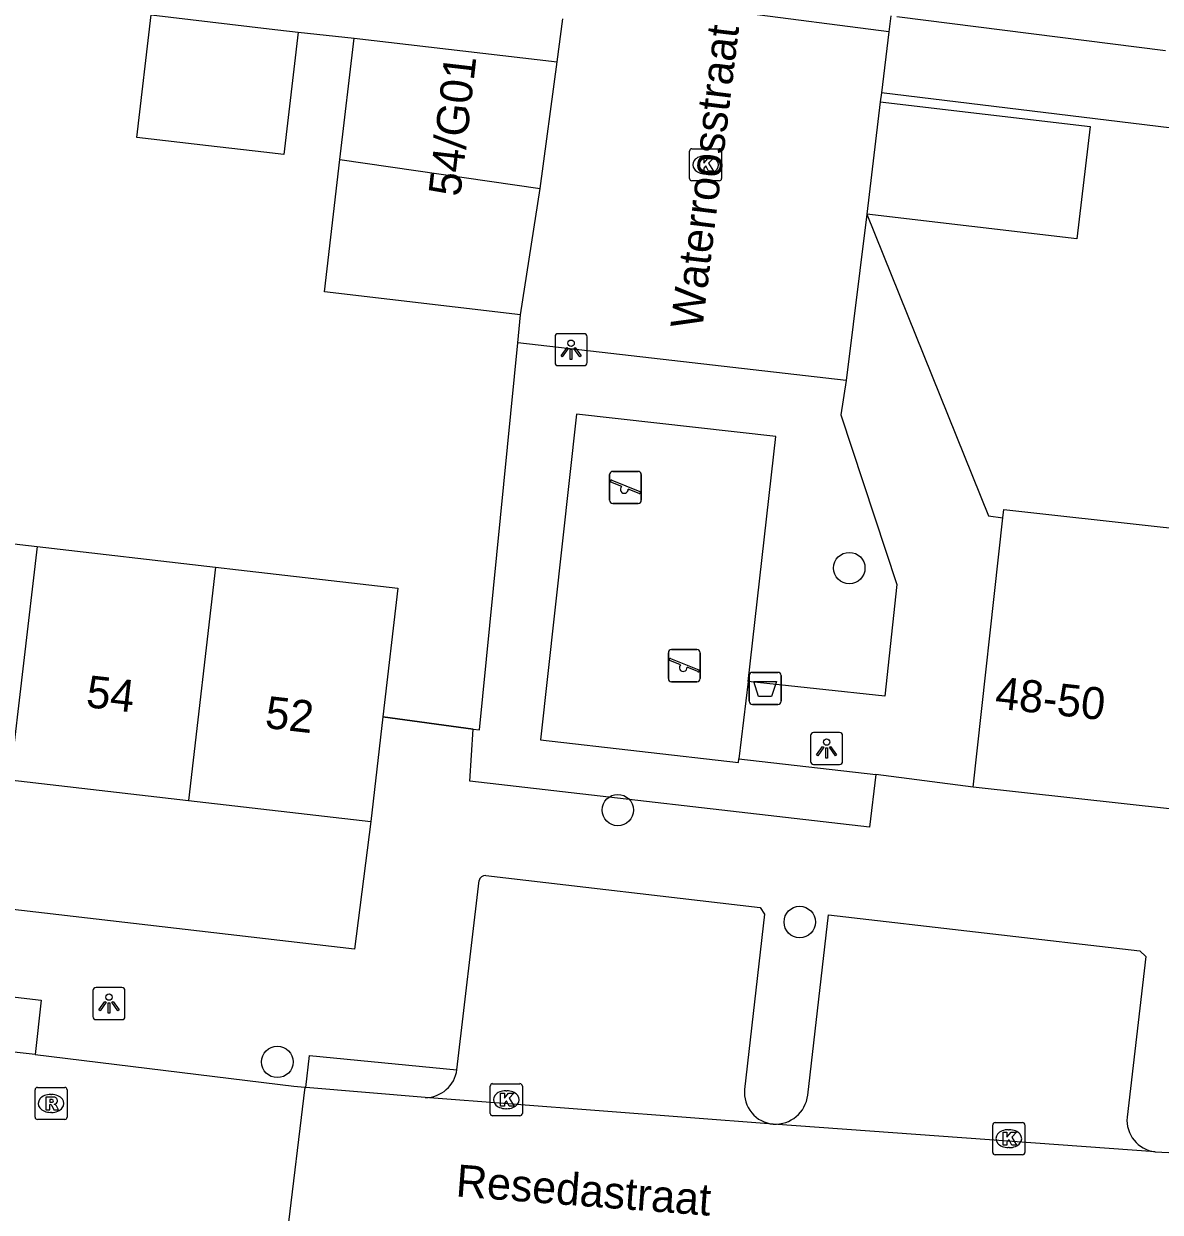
# Model space of a CAD drawing. Extents: x 162250 to 162654, y 380744 to 381605.
# Drawn here: x 162377.07 to 162412.48, y 380893.89 to 380930.93 of the extents above; entities that cross this region are included whole.
import ezdxf

# ---------------------------------------------------------------- set-up
doc = ezdxf.new("R2010")
doc.units = 0
for name, color, linetype in [('IMGEO_Afvalbak', 7, 'Continuous'), ('IMGEO_Boom', 7, 'Continuous'), ('IMGEO_Haag', 7, 'Continuous'), ('IMGEO_Kolk', 7, 'Continuous'), ('IMGEO_Lichtpunt', 7, 'Continuous'), ('IMGEO_Muur', 7, 'Continuous'), ('IMGEO_Openbare_ruimte_label', 7, 'Continuous'), ('IMGEO_Pand', 7, 'Continuous'), ('IMGEO_Pand_nummerreeks', 7, 'Continuous'), ('IMGEO_Rijbaan_lokaal_open', 7, 'Continuous'), ('IMGEO_Rioolput', 7, 'Continuous'), ('IMGEO_Speelvoorziening', 7, 'Continuous'), ('IMGEO_Voetpad_open', 7, 'Continuous')]:
    doc.layers.add(name, color=color, linetype=linetype)

msp = doc.modelspace()

# ---------------------------------------------------------------- linework, layer by layer
at = {"layer": 'IMGEO_Afvalbak'}
for p, q in [((162399.676, 380909.814), (162399.676, 380910.614)), ((162399.676, 380910.614), (162399.676, 380909.814)), ((162399.776, 380910.714), (162400.566, 380910.714)), ((162400.566, 380910.714), (162399.776, 380910.714)), ((162400.666, 380910.614), (162400.666, 380909.814)), ((162400.666, 380909.814), (162400.666, 380910.614)), ((162400.566, 380909.714), (162399.776, 380909.714)), ((162399.776, 380909.714), (162400.566, 380909.714))]:
    msp.add_line(p, q, dxfattribs=at)
msp.add_lwpolyline([(162399.819, 380910.428), (162400.523, 380910.428), (162400.374, 380909.958), (162399.968, 380909.958), (162399.819, 380910.428)], dxfattribs=at)
for centre, start, end in [((162399.776, 380910.614), 90, 180), ((162399.776, 380910.614), 90, 180), ((162400.566, 380910.614), 0, 90), ((162400.566, 380910.614), 360, 90), ((162399.776, 380909.814), 180, 270), ((162399.776, 380909.814), 180, 270), ((162400.566, 380909.814), 270, 0), ((162400.566, 380909.814), 270, 0)]:
    msp.add_arc(centre, 0.1, start, end, dxfattribs=at)
at = {"layer": 'IMGEO_Boom'}
for centre in [(162402.793, 380913.965), (162395.581, 380906.422), (162401.249, 380902.934), (162384.974, 380898.573)]:
    msp.add_circle(centre, 0.489, dxfattribs=at)
at = {"layer": 'IMGEO_Haag'}
for points in [[(162391.079, 380908.948), (162391.269, 380908.923), (162392.465, 380920.986)], [(162399.645, 380910.429), (162400.502, 380918.069), (162394.299, 380918.756), (162393.177, 380908.609), (162399.34, 380907.907), (162399.353, 380908.016)]]:
    msp.add_lwpolyline(points, dxfattribs=at)
at = {"layer": 'IMGEO_Kolk'}
for p, q in [((162397.815, 380926.106), (162397.815, 380926.958)), ((162397.89, 380927.032), (162398.742, 380927.032)), ((162398.303, 380926.812), (162398.328, 380926.812)), ((162398.816, 380926.958), (162398.816, 380926.106)), ((162398.742, 380926.032), (162397.89, 380926.032)), ((162398.326, 380926.252), (162398.301, 380926.252)), ((162391.606, 380896.97), (162391.606, 380897.822)), ((162391.681, 380897.896), (162392.533, 380897.896)), ((162392.607, 380897.822), (162392.607, 380896.97)), ((162392.094, 380897.676), (162392.119, 380897.676)), ((162392.117, 380897.116), (162392.092, 380897.116)), ((162392.533, 380896.896), (162391.681, 380896.896)), ((162407.262, 380895.756), (162407.262, 380896.608)), ((162407.337, 380896.682), (162408.189, 380896.682)), ((162407.75, 380896.462), (162407.775, 380896.462)), ((162408.263, 380896.608), (162408.263, 380895.756)), ((162408.189, 380895.682), (162407.337, 380895.682)), ((162407.773, 380895.902), (162407.748, 380895.902))]:
    msp.add_line(p, q, dxfattribs=at)
for points in [[(162397.815, 380926.106), (162397.815, 380926.958)], [(162397.89, 380927.032), (162398.742, 380927.032)], [(162398.136, 380926.732), (162398.259, 380926.732), (162398.259, 380926.581), (162398.389, 380926.732), (162398.553, 380926.732), (162398.407, 380926.581), (162398.56, 380926.332), (162398.408, 380926.332), (162398.323, 380926.496), (162398.259, 380926.429), (162398.259, 380926.332), (162398.136, 380926.332), (162398.136, 380926.732)], [(162398.816, 380926.958), (162398.816, 380926.106)], [(162398.742, 380926.032), (162397.89, 380926.032)], [(162391.606, 380896.97), (162391.606, 380897.822)], [(162391.681, 380897.896), (162392.533, 380897.896)], [(162392.607, 380897.822), (162392.607, 380896.97)], [(162391.927, 380897.596), (162392.05, 380897.596), (162392.05, 380897.445), (162392.18, 380897.596), (162392.344, 380897.596), (162392.198, 380897.445), (162392.351, 380897.196), (162392.199, 380897.196), (162392.114, 380897.36), (162392.05, 380897.293), (162392.05, 380897.196), (162391.927, 380897.196), (162391.927, 380897.596)], [(162392.533, 380896.896), (162391.681, 380896.896)], [(162407.262, 380895.756), (162407.262, 380896.608)], [(162407.337, 380896.682), (162408.189, 380896.682)], [(162407.583, 380896.382), (162407.706, 380896.382), (162407.706, 380896.231), (162407.836, 380896.382), (162408, 380896.382), (162407.854, 380896.231), (162408.007, 380895.982), (162407.855, 380895.982), (162407.77, 380896.146), (162407.706, 380896.079), (162407.706, 380895.982), (162407.583, 380895.982), (162407.583, 380896.382)], [(162408.263, 380896.608), (162408.263, 380895.756)], [(162408.189, 380895.682), (162407.337, 380895.682)]]:
    msp.add_lwpolyline(points, dxfattribs=at)
for centre, start, end in [((162397.892, 380926.956), 91.552, 178.448), ((162397.892, 380926.956), 91.552, 178.448), ((162398.74, 380926.956), 1.552, 88.448), ((162398.74, 380926.956), 1.552, 88.448), ((162397.892, 380926.108), 181.552, 268.448), ((162397.892, 380926.108), 181.552, 268.448), ((162398.74, 380926.108), 271.552, 358.448), ((162398.74, 380926.108), 271.552, 358.448), ((162391.683, 380897.82), 91.552, 178.448), ((162391.683, 380897.82), 91.552, 178.448), ((162392.531, 380897.82), 1.552, 88.448), ((162392.531, 380897.82), 1.552, 88.448), ((162391.683, 380896.972), 181.552, 268.448), ((162391.683, 380896.972), 181.552, 268.448), ((162392.531, 380896.972), 271.552, 358.448), ((162392.531, 380896.972), 271.552, 358.448), ((162407.339, 380896.606), 91.552, 178.448), ((162407.339, 380896.606), 91.552, 178.448), ((162408.187, 380896.606), 1.552, 88.448), ((162408.187, 380896.606), 1.552, 88.448), ((162407.339, 380895.758), 181.552, 268.448), ((162407.339, 380895.758), 181.552, 268.448), ((162408.187, 380895.758), 271.552, 358.448), ((162408.187, 380895.758), 271.552, 358.448)]:
    msp.add_arc(centre, 0.0765, start, end, dxfattribs=at)
for centre, major_axis, ratio, start_param, end_param in [((162398.302, 380926.532), (-0.387, 0.002), 0.722429, 4.712389, 7.853982), ((162398.327, 380926.532), (-0.39, 0.002), 0.717154, 1.570796, 4.712389), ((162392.093, 380897.396), (-0.387, 0.002), 0.722429, 4.712389, 7.853982), ((162392.118, 380897.396), (-0.39, 0.002), 0.717154, 1.570796, 4.712389), ((162407.749, 380896.182), (-0.387, 0.002), 0.722429, 4.712389, 7.853982), ((162407.774, 380896.182), (-0.39, 0.002), 0.717154, 1.570796, 4.712389)]:
    msp.add_ellipse(centre, major_axis=major_axis, ratio=ratio, start_param=start_param, end_param=end_param, dxfattribs=at)
at = {"layer": 'IMGEO_Lichtpunt'}
for p, q in [((162393.626, 380921.174), (162393.626, 380920.367)), ((162393.626, 380921.174), (162393.626, 380920.367)), ((162394.528, 380921.269), (162393.72, 380921.269)), ((162394.528, 380921.269), (162393.72, 380921.269)), ((162394.622, 380920.367), (162394.622, 380921.174)), ((162394.622, 380920.367), (162394.622, 380921.174)), ((162393.72, 380920.273), (162394.528, 380920.273)), ((162393.72, 380920.273), (162394.528, 380920.273)), ((162401.588, 380908.744), (162401.588, 380907.937)), ((162401.588, 380908.744), (162401.588, 380907.937)), ((162402.49, 380908.839), (162401.682, 380908.839)), ((162402.49, 380908.839), (162401.682, 380908.839)), ((162402.584, 380907.937), (162402.584, 380908.744)), ((162402.584, 380907.937), (162402.584, 380908.744)), ((162401.682, 380907.843), (162402.49, 380907.843)), ((162401.682, 380907.843), (162402.49, 380907.843)), ((162379.231, 380900.795), (162379.231, 380899.988)), ((162379.231, 380900.795), (162379.231, 380899.988)), ((162380.133, 380900.89), (162379.325, 380900.89)), ((162380.133, 380900.89), (162379.325, 380900.89)), ((162380.227, 380899.988), (162380.227, 380900.795)), ((162380.227, 380899.988), (162380.227, 380900.795)), ((162379.325, 380899.894), (162380.133, 380899.894)), ((162379.325, 380899.894), (162380.133, 380899.894))]:
    msp.add_line(p, q, dxfattribs=at)
for points in [[(162394, 380920.838), (162394.039, 380920.81), (162393.851, 380920.548), (162393.813, 380920.575), (162394, 380920.838)], [(162394.102, 380920.79), (162394.149, 380920.79), (162394.149, 380920.468), (162394.102, 380920.468), (162394.102, 380920.79)], [(162394.212, 380920.81), (162394.25, 380920.837), (162394.437, 380920.575), (162394.398, 380920.547), (162394.212, 380920.81)], [(162401.962, 380908.408), (162402.001, 380908.38), (162401.813, 380908.118), (162401.775, 380908.145), (162401.962, 380908.408)], [(162402.064, 380908.36), (162402.111, 380908.36), (162402.111, 380908.038), (162402.064, 380908.038), (162402.064, 380908.36)], [(162402.174, 380908.38), (162402.212, 380908.407), (162402.399, 380908.145), (162402.36, 380908.117), (162402.174, 380908.38)], [(162379.605, 380900.459), (162379.644, 380900.431), (162379.456, 380900.169), (162379.418, 380900.196), (162379.605, 380900.459)], [(162379.707, 380900.411), (162379.754, 380900.411), (162379.754, 380900.089), (162379.707, 380900.089), (162379.707, 380900.411)], [(162379.817, 380900.431), (162379.855, 380900.458), (162380.042, 380900.196), (162380.003, 380900.168), (162379.817, 380900.431)]]:
    msp.add_lwpolyline(points, dxfattribs=at)
for centre in [(162394.125, 380920.972), (162402.087, 380908.542), (162379.73, 380900.593)]:
    msp.add_circle(centre, 0.0994, dxfattribs=at)
for centre, start, end in [((162393.72, 380921.174), 90, 180), ((162393.72, 380921.174), 90, 180), ((162394.528, 380921.174), 0, 90), ((162394.528, 380921.174), 0, 90), ((162393.72, 380920.367), 180, 270), ((162393.72, 380920.367), 180, 270), ((162394.528, 380920.367), 270, 0), ((162394.528, 380920.367), 270, 360), ((162401.682, 380908.744), 90, 180), ((162401.682, 380908.744), 90, 180), ((162402.49, 380908.744), 0, 90), ((162402.49, 380908.744), 0, 90), ((162401.682, 380907.937), 180, 270), ((162401.682, 380907.937), 180, 270), ((162402.49, 380907.937), 270, 0), ((162402.49, 380907.937), 270, 360), ((162379.325, 380900.795), 90, 180), ((162379.325, 380900.795), 90, 180), ((162380.133, 380900.795), 0, 90), ((162380.133, 380900.795), 0, 90), ((162379.325, 380899.988), 180, 270), ((162379.325, 380899.988), 180, 270), ((162380.133, 380899.988), 270, 0), ((162380.133, 380899.988), 270, 360)]:
    msp.add_arc(centre, 0.0946, start, end, dxfattribs=at)
at = {"layer": 'IMGEO_Muur'}
for points in [[(162392.465, 380920.986), (162392.552, 380921.858)], [(162391.079, 380908.948), (162391.269, 380908.923), (162392.465, 380920.986)], [(162388.264, 380909.325), (162391.079, 380908.948)]]:
    msp.add_lwpolyline(points, dxfattribs=at)
at = {"layer": 'IMGEO_Pand'}
for points in [[(162385.623, 380930.668), (162385.179, 380926.849), (162384.55, 380926.922), (162382.83, 380927.122), (162380.598, 380927.382), (162381.042, 380931.201)], [(162381.042, 380931.201), (162384.718, 380930.773), (162384.994, 380930.741), (162385.623, 380930.668)], [(162404.27, 380931.15), (162412.639, 380930.091)], [(162386.923, 380926.699), (162387.365, 380930.48)], [(162387.365, 380930.48), (162393.695, 380929.741)], [(162393.167, 380925.793), (162393.695, 380929.741)], [(162403.759, 380928.497), (162410.295, 380927.721), (162409.879, 380924.221), (162403.344, 380924.995)], [(162403.759, 380928.497), (162403.344, 380924.995)], [(162392.552, 380921.858), (162386.44, 380922.572), (162386.923, 380926.699)], [(162386.923, 380926.699), (162393.167, 380925.793)], [(162392.552, 380921.858), (162393.167, 380925.793)], [(162407.575, 380915.525), (162407.604, 380915.79), (162412.574, 380915.242), (162413.861, 380915.1)], [(162371.924, 380915.282), (162377.487, 380914.637)], [(162406.649, 380907.132), (162407.575, 380915.525)], [(162377.487, 380914.637), (162376.642, 380907.369)], [(162377.487, 380914.637), (162383.048, 380913.992)], [(162383.048, 380913.992), (162382.204, 380906.725)], [(162383.048, 380913.992), (162383.762, 380913.91), (162388.728, 380913.334), (162388.264, 380909.325)], [(162388.264, 380909.325), (162387.886, 380906.066)], [(162376.642, 380907.369), (162382.204, 380906.725)], [(162412.864, 380906.447), (162406.649, 380907.132)], [(162382.204, 380906.725), (162387.886, 380906.066)]]:
    msp.add_lwpolyline(points, dxfattribs=at)
at = {"layer": 'IMGEO_Rijbaan_lokaal_open'}
for points in [[(162404.024, 380930.68), (162399.359, 380931.282), (162401.19, 380947.056)], [(162393.695, 380929.741), (162393.868, 380931.08)], [(162404.024, 380930.68), (162403.792, 380928.77)], [(162403.792, 380928.77), (162403.759, 380928.497)], [(162403.344, 380924.995), (162402.7, 380919.808)], [(162392.465, 380920.986), (162392.552, 380921.858)], [(162402.7, 380919.808), (162392.465, 380920.986)], [(162377.427, 380898.803), (162372.076, 380899.395)], [(162377.427, 380898.803), (162385.493, 380897.823), (162385.826, 380897.783)], [(162385.826, 380897.783), (162385.279, 380893.239)], [(162385.826, 380897.783), (162385.866, 380897.778)], [(162389.579, 380897.463), (162385.866, 380897.778)], [(162400.423, 380896.635), (162389.579, 380897.463)], [(162412.32, 380895.776), (162400.423, 380896.635)], [(162412.32, 380895.776), (162412.957, 380895.742)]]:
    msp.add_lwpolyline(points, dxfattribs=at)
at = {"layer": 'IMGEO_Rioolput'}
for p, q in [((162377.426, 380896.854), (162377.426, 380897.706)), ((162377.501, 380897.78), (162378.353, 380897.78)), ((162377.914, 380897.56), (162377.939, 380897.56)), ((162378.427, 380897.706), (162378.427, 380896.854)), ((162378.353, 380896.78), (162377.501, 380896.78)), ((162377.937, 380897), (162377.912, 380897))]:
    msp.add_line(p, q, dxfattribs=at)
for points in [[(162377.426, 380896.854), (162377.426, 380897.706)], [(162377.501, 380897.78), (162378.353, 380897.78)], [(162378.015, 380897.478), (162377.763, 380897.48), (162377.763, 380897.08)], [(162378.427, 380897.706), (162378.427, 380896.854)], [(162377.763, 380897.08), (162377.887, 380897.08), (162377.887, 380897.242), (162377.898, 380897.242)], [(162377.941, 380897.399), (162377.887, 380897.399), (162377.887, 380897.318)], [(162377.887, 380897.318), (162377.939, 380897.318)], [(162377.945, 380897.213), (162378.016, 380897.08), (162378.156, 380897.08), (162378.091, 380897.206)], [(162378.353, 380896.78), (162377.501, 380896.78)]]:
    msp.add_lwpolyline(points, dxfattribs=at)
for centre, radius, start, end in [((162377.503, 380897.704), 0.0765, 91.552, 178.448), ((162377.503, 380897.704), 0.0765, 91.552, 178.448), ((162378.014, 380897.368), 0.109, 350.3612, 89.416), ((162378.351, 380897.704), 0.0765, 1.552, 88.448), ((162378.351, 380897.704), 0.0765, 1.552, 88.448), ((162377.897, 380897.189), 0.0533, 26.0293, 88.6989), ((162377.923, 380897.507), 0.19, 274.7715, 282.9687), ((162377.947, 380897.303), 0.0964, 77.0061, 93.1865), ((162377.961, 380897.36), 0.0378, 276.6634, 79.6772), ((162378.012, 380897.368), 0.112, 277.5842, 350.9817), ((162377.996, 380897.153), 0.108, 29.5134, 73.7905), ((162377.503, 380896.856), 0.0765, 181.552, 268.448), ((162377.503, 380896.856), 0.0765, 181.552, 268.448), ((162378.351, 380896.856), 0.0765, 271.552, 358.448), ((162378.351, 380896.856), 0.0765, 271.552, 358.448)]:
    msp.add_arc(centre, radius, start, end, dxfattribs=at)
for centre, major_axis, ratio, start_param, end_param in [((162377.913, 380897.28), (-0.387, 0.002), 0.722429, 4.712389, 7.853982), ((162377.938, 380897.28), (-0.39, 0.002), 0.717154, 1.570796, 4.712389)]:
    msp.add_ellipse(centre, major_axis=major_axis, ratio=ratio, start_param=start_param, end_param=end_param, dxfattribs=at)
at = {"layer": 'IMGEO_Speelvoorziening'}
for p, q in [((162395.323, 380916.077), (162395.323, 380916.877)), ((162395.323, 380916.877), (162395.323, 380916.077)), ((162395.423, 380916.977), (162396.213, 380916.977)), ((162396.213, 380916.977), (162395.423, 380916.977)), ((162396.313, 380916.877), (162396.313, 380916.077)), ((162396.313, 380916.077), (162396.313, 380916.877)), ((162395.706, 380916.505), (162395.367, 380916.642)), ((162395.392, 380916.702), (162396.268, 380916.349)), ((162396.244, 380916.289), (162395.904, 380916.426)), ((162396.213, 380915.977), (162395.423, 380915.977)), ((162395.423, 380915.977), (162396.213, 380915.977)), ((162397.156, 380910.524), (162397.156, 380911.324)), ((162397.156, 380911.324), (162397.156, 380910.524)), ((162397.256, 380911.424), (162398.046, 380911.424)), ((162398.046, 380911.424), (162397.256, 380911.424)), ((162398.146, 380911.324), (162398.146, 380910.524)), ((162398.146, 380910.524), (162398.146, 380911.324)), ((162397.539, 380910.952), (162397.2, 380911.089)), ((162397.225, 380911.149), (162398.101, 380910.796)), ((162398.077, 380910.736), (162397.737, 380910.873)), ((162398.046, 380910.424), (162397.256, 380910.424)), ((162397.256, 380910.424), (162398.046, 380910.424))]:
    msp.add_line(p, q, dxfattribs=at)
for centre, radius, start, end in [((162395.423, 380916.877), 0.1, 90, 180), ((162395.423, 380916.877), 0.1, 90, 180), ((162396.213, 380916.877), 0.1, 0, 90), ((162396.213, 380916.877), 0.1, 360, 90), ((162395.38, 380916.672), 0.0327, 68.078, 248.078), ((162395.785, 380916.415), 0.12, 130.9928, 5.1632), ((162396.256, 380916.319), 0.0327, 248.078, 68.078), ((162395.423, 380916.077), 0.1, 180, 270), ((162395.423, 380916.077), 0.1, 180, 270), ((162396.213, 380916.077), 0.1, 270, 0), ((162396.213, 380916.077), 0.1, 270, 0), ((162397.256, 380911.324), 0.1, 90, 180), ((162397.256, 380911.324), 0.1, 90, 180), ((162397.213, 380911.119), 0.0327, 68.078, 248.078), ((162398.046, 380911.324), 0.1, 0, 90), ((162398.046, 380911.324), 0.1, 360, 90), ((162397.618, 380910.862), 0.12, 130.9928, 5.1632), ((162398.089, 380910.766), 0.0327, 248.078, 68.078), ((162397.256, 380910.524), 0.1, 180, 270), ((162397.256, 380910.524), 0.1, 180, 270), ((162398.046, 380910.524), 0.1, 270, 0), ((162398.046, 380910.524), 0.1, 270, 0)]:
    msp.add_arc(centre, radius, start, end, dxfattribs=at)
at = {"layer": 'IMGEO_Voetpad_open'}
for points in [[(162404.084, 380931.173), (162404.024, 380930.68)], [(162385.623, 380930.668), (162387.365, 380930.48)], [(162413.181, 380927.63), (162403.792, 380928.77)], [(162403.344, 380924.995), (162407.129, 380915.597), (162407.575, 380915.525)], [(162402.7, 380919.808), (162402.527, 380918.737), (162404.275, 380913.449), (162403.901, 380909.972), (162399.645, 380910.429)], [(162387.886, 380906.066), (162387.38, 380902.085), (162303.756, 380911.805)], [(162399.645, 380910.429), (162399.353, 380908.016)], [(162391.079, 380908.948), (162388.264, 380909.325)], [(162403.615, 380907.534), (162403.427, 380905.895), (162390.97, 380907.322), (162391.079, 380908.948)], [(162399.353, 380908.016), (162403.615, 380907.534)], [(162406.649, 380907.132), (162403.615, 380907.534)], [(162342.278, 380903.526), (162342.387, 380904.63), (162377.614, 380900.501), (162377.427, 380898.803)], [(162390.571, 380898.331), (162391.259, 380904.226)], [(162391.469, 380904.384), (162400.014, 380903.385), (162400.147, 380903.183), (162399.528, 380897.712)], [(162401.498, 380897.54), (162402.141, 380903.159), (162411.845, 380902.031), (162412.031, 380901.861), (162411.447, 380896.85)], [(162385.866, 380897.778), (162385.974, 380898.769), (162390.571, 380898.331)]]:
    msp.add_lwpolyline(points, dxfattribs=at)
for centre, radius, start, end in [((162391.446, 380904.195), 0.19, 83.1734, 170.7408), ((162389.578, 380898.465), 1.002, 270.0487, 352.3231), ((162400.513, 380897.62), 0.989, 174.6666, 264.7873), ((162400.484, 380897.654), 1.021, 266.589, 353.5964), ((162412.431, 380896.758), 0.989, 174.6787, 263.5331)]:
    msp.add_arc(centre, radius, start, end, dxfattribs=at)

# ---------------------------------------------------------------- texts
at = {"layer": 'IMGEO_Openbare_ruimte_label'}
for s, rotation, p in [('Waterroosstraat', 83.0526, (162398.211, 380921.382)), ('Resedastraat', 355.6408, (162390.515, 380894.384))]:
    msp.add_text(s, height=1, rotation=rotation, dxfattribs=at).set_placement(p)
at = {"layer": 'IMGEO_Pand_nummerreeks'}
for s, rotation, p in [('54/G01', 83.4001, (162390.673, 380925.518)), ('54', 353.3879, (162378.988, 380909.635)), ('48-50', 353.7085, (162407.307, 380909.595)), ('52', 353.3879, (162384.563, 380908.988))]:
    msp.add_text(s, height=1, rotation=rotation, dxfattribs=at).set_placement(p)

doc.saveas('drawing.dxf')
